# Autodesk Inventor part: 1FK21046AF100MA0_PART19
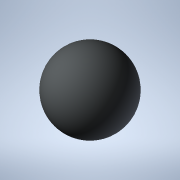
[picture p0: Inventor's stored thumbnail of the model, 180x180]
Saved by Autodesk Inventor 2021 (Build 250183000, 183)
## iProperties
Created: 2025-04
Part Number: 1FK21046AF100MA0_PART19
Material: Generic
Catalog Web Link: www.3dfindit.com
Description: -Servo synchronous motor
Document SubType Name: Modeling
Designer: psAdmin
Mass: 0.137258 g
Surface Area: 1.2868 cm^2
Volume: 0.137258 cm^3
Density: 1 g/cm^3
Appearance: PSOLRGB-212-217-219
Category: PARTsolutions
Title: 1FK21046AF100MA0_PART19
Author: Cadenas PARTsolutions
Comments: Servo synchronous motor
Sending System: PARTsolutions
Preprocessor: ST-DEVELOPER v19.3
PSOL_IDENT_0: {$CADENAS_DATA/23d-libs/siemens_ag/_cat_/4f/2b/1fk21046af100ma0.prj},216 {VTYP=3D},{NB=1FK21046AF100
PSOL_IDENT_1: MA0_PART19},{LINA=1FK21046AF100MA0_PART19},{NN=1FK21046AF100MA0_PART19},{NOPRJ=TRUE},{DATE=19.08.202
PSOL_IDENT_2: 5 14:00:37},{GEOMDATE=30.07.2025 02:01:06},{VERSION=},{LINEID=10},{WBVAR=},{WBNUMERIC=}  {NB=1FK2104
PSOL_IDENT_3: 6AF100MA0_PART19},{LINA=1FK21046AF100MA0_PART19},{KT=DUMMY},{PREVIEW=../../../_pool_/cb/72/p_d211_xx
PSOL_IDENT_4: _00434j.png},{DESCSHORT=SIMOTICS S-1FK2 HD, SINAMICS S210 3AC 400V-480V, 3.2 Nm, 3000 rpm},{DESCLONG=
PSOL_IDENT_5: SIMOTICS S-1FK2 HD servo motor M0=3.2 Nm; PN = 1 kW at nN=3000 rpm (380-480 V); PN = 0.5 kW at nN=15
PSOL_IDENT_6: 00 rpm (200-240 V); with holding brake; degree of protection IP64; cylindrical shaft D19x40mm; absol
PSOL_IDENT_7: ute encoder 22-bit + 12-bit multiturn (encoder AM22DQC); with OCC interface; plug size M17, rotatabl
PSOL_IDENT_8: e; SIMOTICS S-1FK2 servomotorfor a wide range of uses in industrial environments. SIMOTICS S‑1FK2 se
PSOL_IDENT_9: rvomotors are compact synchronous motors with a high dynamic performance that set themselves apart a
PSOL_IDENT_10: s a result of their high power density, degree of protection and overload capability. The motors are
PSOL_IDENT_11: available in two variants: as High Dynamic variant (highest dynamic performance as a result of the
PSOL_IDENT_12: low intrinsic moment of inertia for applications demanding a high dynamic performance with low moved
PSOL_IDENT_13: masses) - and as Compact variant (precise and stable closed-loop control for medium up to large mov
PSOL_IDENT_14: ed masses as a result of a medium intrinsic moment of inertia). SIMOTICSS‑1FK2 servomotors fully exp
PSOL_IDENT_15: loit their strengths in a system with the SINAMICSS210 frequency converter and simple connection usi
PSOL_IDENT_16: ng the one cable connection (OCC). Advantages include the short control and positioning times, fast
PSOL_IDENT_17: and precise correction of disturbing quantities as well as stable control with a high dynamic perfor
PSOL_IDENT_18: mance. The servo motors can be configured to address a wide range of requirements. For example with
PSOL_IDENT_19: and without holding brake, IP64 or IP65 degree of protection, singleturn or multiturn absolute encod
PSOL_IDENT_20: ers - to name just a few. Further, the servomotors are available in different shaft heights extendin
PSOL_IDENT_21: g from 20 to 100. A shaft sealing ring is available to achieve an IP65 degree of protection and for
PSOL_IDENT_22: subsequent mounting at the motor or as spare part. SIMOTICS - the optimum motor for each and every m
PSOL_IDENT_23: otion control application.},{INTNO=195125049673},{SUPPLIERALTNO=1FK2104-6AF10-0MA0},{MANUID=1FK21046
PSOL_IDENT_24: AF100MA0},{MANUNAME=Siemens},{MANUTYPEDESC=Synchronous motor 1FK2-HD 3.2 NM},{AAU732=SIMOTICS},{AAO0
PSOL_IDENT_25: 57=S-1FK2},{AAU734=SIMOTICS S-1FK2 HD servo motor M0=3.2 Nm; PN = 1 kW at nN=3000 rpm (380-480 V); P
PSOL_IDENT_26: N = 0.5 kW at nN=1500 rpm (200-240 V); with holding brake; degree of protection IP64; cylindrical sh
PSOL_IDENT_27: aft D19x40mm; absolute encoder 22-bit + 12-bit multiturn (encoder AM22DQC); with OCC interface; plug
PSOL_IDENT_28: size M17, rotatable;},{AAW338=Synchronous motor 1FK2-HD 3.2 NM},{AAO742=SIMOTICS},{AAO663=404294869
PSOL_IDENT_29: 4534},{NOCUPEROU=1},{PRICEQUANTITY=1},{QUANTITYMIN=1},{QUANTITYINT=1},{CTN=85015220},{COO=DE},{AAO67
PSOL_IDENT_30: 6=1FK2104-6AF10-0MA0},{AAO677=Siemens AG},{ORDERUNIT=C62},{CONTENTUNIT=C62}
NB: 1FK21046AF100MA0_PART19
NT: Servo synchronous motor
NBSYN: $MANUID._PART19
LINA: 1FK21046AF100MA0_PART19
CATALOG: SIEMENS
PREVIEW: ../../../_pool_/cb/72/p_d211_xx_00434j.png
DESCSHORT: SIMOTICS S-1FK2 HD, SINAMICS S210 3AC 400V-480V, 3.2 Nm, 3000 rpm
DESCLONG: SIMOTICS S-1FK2 HD servo motor M0=3.2 Nm; PN = 1 kW at nN=3000 rpm (380-480 V); PN = 0.5 kW at nN=1500 rpm (200-240 V); with holding brake; degree of protection
INTNO: 195125049673
SUPPLIERALTNO: 1FK2104-6AF10-0MA0
MANUID: 1FK21046AF100MA0
MANUNAME: Siemens
MANUTYPEDESC: Synchronous motor 1FK2-HD 3.2 NM
AAU732: SIMOTICS
AAO057: S-1FK2
AAU734: SIMOTICS S-1FK2 HD servo motor M0=3.2 Nm; PN = 1 kW at nN=3000 rpm (380-480 V); PN = 0.5 kW at nN=1500 rpm (200-240 V); with holding brake; degree of protection
AAW338: Synchronous motor 1FK2-HD 3.2 NM
AAO742: SIMOTICS
AAO663: 4042948694534.0
NOCUPEROU: 1
PRICEQUANTITY: 1
QUANTITYMIN: 1
QUANTITYINT: 1
CTN: 85015220
COO: DE
ARTICLENO: 1FK21046AF100MA0_PART19
BOMINFO: 1FK21046AF100MA0_PART19
CREATOR: CADENAS GmbH
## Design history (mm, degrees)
feature "2025_04_17_14_59_39_0177"
body "Solid1"
